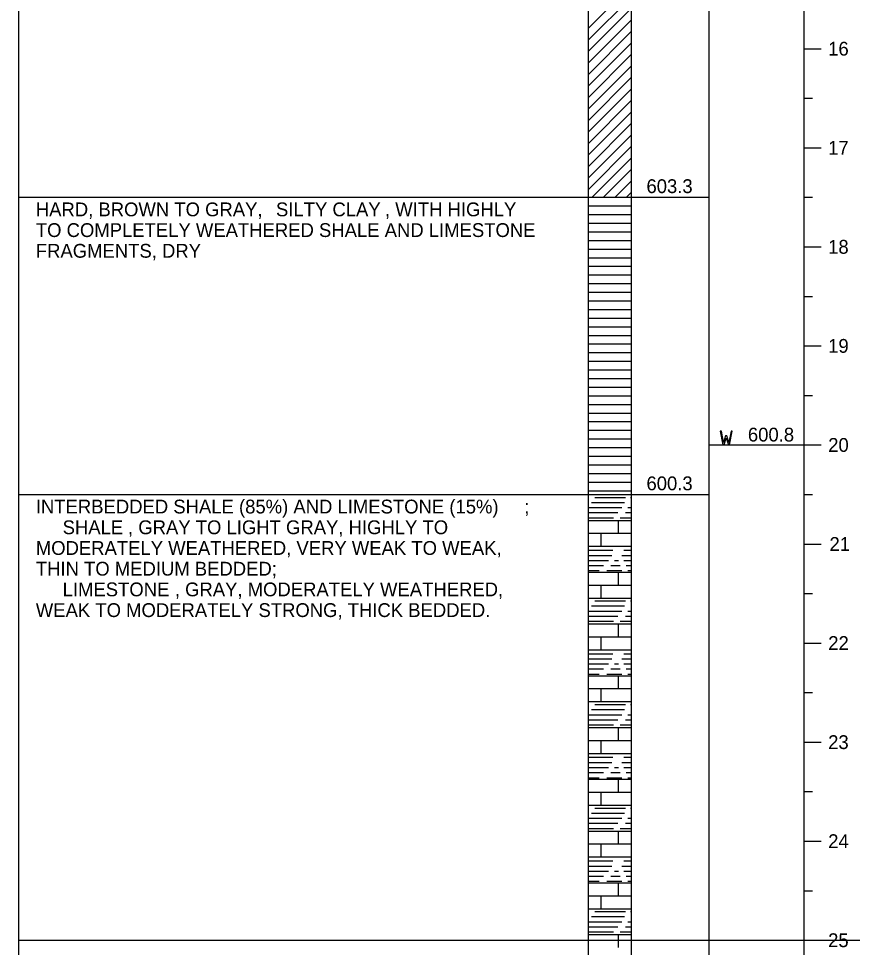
# Model space of a CAD drawing. Extents: x 0 to 0.83, y -0.65 to 1.27.
# Drawn here: x 0 to 0.4026, y -0.0035 to 0.4451 of the extents above; entities that cross this region are included whole.
import ezdxf

# ---------------------------------------------------------------- set-up
doc = ezdxf.new("R2010")
doc.units = 0

# ---------------------------------------------------------------- blocks, each defined once
blk = doc.blocks.new('DGRFC!OHDOT FREE WATER')
blk.add_lwpolyline([(-0.00161, 0), (-0.00102, 0), (0, 0.00346), (0.00102, 0), (0.00161, 0), (0.00292, 0.00667), (0.00233, 0.00667), (0.00126, 0.00118), (0.00029, 0.00444), (-0.00029, 0.00444), (-0.00126, 0.00118), (-0.00233, 0.00667), (-0.00292, 0.00667)], close=True)

msp = doc.modelspace()

# ---------------------------------------------------------------- linework, layer by layer
msp.add_lwpolyline([(0, 0), (0.83333, 0), (0.83333, 1.275), (0, 1.275)], close=True)
msp.add_lwpolyline([(0, 0), (0.83333, 0), (0.83333, 1.275), (0, 1.275)], close=True)
msp.add_lwpolyline([(0, 0), (0.83333, 0), (0.83333, 1.275), (0, 1.275)], close=True)
msp.add_lwpolyline([(0, 0), (0.83333, 0), (0.83333, 1.275), (0, 1.275)], close=True)
msp.add_lwpolyline([(0, 0), (0.83333, 0), (0.83333, 1.275), (0, 1.275)], close=True)
for points in [[(0.29583, 1.22083), (0.29583, -0.64575)], [(0.29583, 1.22083), (0.29583, -0.64575)], [(0.33333, 1.22083), (0.33333, -0.64575)], [(0.33333, 1.22083), (0.33333, -0.64575)], [(0.275, 1.19583), (0.275, -0.64575)], [(0.37917, 1.19583), (0.37917, -0.64575)], [(0.275, 0.64575), (0.275, 0.35875)], [(0.275, 0.44019), (0.29583, 0.46103)], [(0.275, 0.43464), (0.29583, 0.45547)], [(0.275, 0.42908), (0.29583, 0.44992)], [(0.275, 0.42353), (0.29583, 0.44436)], [(0.275, 0.41797), (0.29583, 0.4388)], [(0.275, 0.41242), (0.29583, 0.43325)], [(0.275, 0.40686), (0.29583, 0.42769)], [(0.37917, 0.4305), (0.3875, 0.4305)], [(0.37917, 0.4305), (0.38333, 0.4305)], [(0.275, 0.4013), (0.29583, 0.42214)], [(0.275, 0.39575), (0.29583, 0.41658)], [(0.275, 0.39019), (0.29583, 0.41103)], [(0.275, 0.38464), (0.29583, 0.40547)], [(0.37917, 0.40658), (0.38333, 0.40658)], [(0.275, 0.37908), (0.29583, 0.39992)], [(0.275, 0.37353), (0.29583, 0.39436)], [(0.275, 0.36797), (0.29583, 0.3888)], [(0.275, 0.36242), (0.29583, 0.38325)], [(0.37917, 0.38267), (0.3875, 0.38267)], [(0.37917, 0.38267), (0.38333, 0.38267)], [(0.27689, 0.35875), (0.29583, 0.37769)], [(0.28244, 0.35875), (0.29583, 0.37214)], [(0.288, 0.35875), (0.29583, 0.36658)], [(0.29355, 0.35875), (0.29583, 0.36103)], [(0, 0.35875), (0.275, 0.35875)], [(0.275, 0.35875), (0.29583, 0.35875)], [(0.275, 0.35875), (0.29583, 0.35875)], [(0.275, 0.35875), (0.275, 0.21525)], [(0.275, 0.35458), (0.29583, 0.35458)], [(0.29583, 0.35875), (0.33333, 0.35875)], [(0.37917, 0.35875), (0.38333, 0.35875)], [(0.275, 0.35042), (0.29583, 0.35042)], [(0.275, 0.34625), (0.29583, 0.34625)], [(0.275, 0.34208), (0.29583, 0.34208)], [(0.275, 0.33792), (0.29583, 0.33792)], [(0.275, 0.33375), (0.29583, 0.33375)], [(0.37917, 0.33483), (0.3875, 0.33483)], [(0.37917, 0.33483), (0.38333, 0.33483)], [(0.275, 0.32958), (0.29583, 0.32958)], [(0.275, 0.32542), (0.29583, 0.32542)], [(0.275, 0.32125), (0.29583, 0.32125)], [(0.275, 0.31708), (0.29583, 0.31708)], [(0.275, 0.31292), (0.29583, 0.31292)], [(0.37917, 0.31092), (0.38333, 0.31092)], [(0.275, 0.30875), (0.29583, 0.30875)], [(0.275, 0.30458), (0.29583, 0.30458)], [(0.275, 0.30042), (0.29583, 0.30042)], [(0.275, 0.29625), (0.29583, 0.29625)], [(0.275, 0.29208), (0.29583, 0.29208)], [(0.275, 0.28792), (0.29583, 0.28792)], [(0.275, 0.28375), (0.29583, 0.28375)], [(0.37917, 0.287), (0.3875, 0.287)], [(0.37917, 0.287), (0.38333, 0.287)], [(0.275, 0.27958), (0.29583, 0.27958)], [(0.275, 0.27542), (0.29583, 0.27542)], [(0.275, 0.27125), (0.29583, 0.27125)], [(0.275, 0.26708), (0.29583, 0.26708)], [(0.275, 0.26292), (0.29583, 0.26292)], [(0.37917, 0.26308), (0.38333, 0.26308)], [(0.275, 0.25875), (0.29583, 0.25875)], [(0.275, 0.25458), (0.29583, 0.25458)], [(0.275, 0.25042), (0.29583, 0.25042)], [(0.275, 0.24625), (0.29583, 0.24625)], [(0.275, 0.24208), (0.29583, 0.24208)], [(0.275, 0.23792), (0.29583, 0.23792)], [(0.33333, 0.23917), (0.37917, 0.23917)], [(0.37917, 0.23917), (0.3875, 0.23917)], [(0.37917, 0.23917), (0.38333, 0.23917)], [(0.275, 0.23375), (0.29583, 0.23375)], [(0.275, 0.22958), (0.29583, 0.22958)], [(0.275, 0.22542), (0.29583, 0.22542)], [(0.275, 0.22125), (0.29583, 0.22125)], [(0.275, 0.21708), (0.29583, 0.21708)], [(0, 0.21525), (0.275, 0.21525)], [(0.275, 0.21525), (0.29583, 0.21525)], [(0.275, 0.21525), (0.29583, 0.21525)], [(0.275, 0.21525), (0.275, -0.64575)], [(0.27667, 0.21142), (0.29258, 0.21142)], [(0.27825, 0.21383), (0.293, 0.21383)], [(0.29542, 0.21383), (0.29583, 0.21383)], [(0.29583, 0.21525), (0.33333, 0.21525)], [(0.37917, 0.21525), (0.38333, 0.21525)], [(0.275, 0.20892), (0.29133, 0.20892)], [(0.275, 0.2065), (0.28933, 0.2065)], [(0.293, 0.2065), (0.29583, 0.2065)], [(0.29417, 0.20892), (0.29583, 0.20892)], [(0.275, 0.204), (0.28725, 0.204)], [(0.275, 0.20275), (0.29583, 0.20275)], [(0.28958, 0.1965), (0.28958, 0.20275)], [(0.2905, 0.204), (0.29583, 0.204)], [(0.275, 0.1965), (0.29583, 0.1965)], [(0.28125, 0.19025), (0.28125, 0.1965)], [(0.275, 0.19025), (0.29583, 0.19025)], [(0.37917, 0.19133), (0.3875, 0.19133)], [(0.37917, 0.19133), (0.38333, 0.19133)], [(0.275, 0.18833), (0.28683, 0.18833)], [(0.275, 0.18583), (0.28642, 0.18583)], [(0.29133, 0.18583), (0.29583, 0.18583)], [(0.29217, 0.18833), (0.29583, 0.18833)], [(0.275, 0.18342), (0.28483, 0.18342)], [(0.275, 0.181), (0.28233, 0.181)], [(0.286, 0.181), (0.2905, 0.181)], [(0.28767, 0.18342), (0.28967, 0.18342)], [(0.29217, 0.18342), (0.29583, 0.18342)], [(0.29342, 0.181), (0.29583, 0.181)], [(0.275, 0.1785), (0.28033, 0.1785)], [(0.275, 0.17775), (0.29583, 0.17775)], [(0.284, 0.1785), (0.29133, 0.1785)], [(0.28958, 0.1715), (0.28958, 0.17775)], [(0.29417, 0.1785), (0.29583, 0.1785)], [(0.275, 0.1715), (0.29583, 0.1715)], [(0.28125, 0.16525), (0.28125, 0.1715)], [(0.37917, 0.16742), (0.38333, 0.16742)], [(0.275, 0.16525), (0.29583, 0.16525)], [(0.27825, 0.16383), (0.293, 0.16383)], [(0.29542, 0.16383), (0.29583, 0.16383)], [(0.275, 0.15892), (0.29133, 0.15892)], [(0.27667, 0.16142), (0.29258, 0.16142)], [(0.29417, 0.15892), (0.29583, 0.15892)], [(0.275, 0.1565), (0.28933, 0.1565)], [(0.275, 0.154), (0.28725, 0.154)], [(0.275, 0.15275), (0.29583, 0.15275)], [(0.28958, 0.1465), (0.28958, 0.15275)], [(0.2905, 0.154), (0.29583, 0.154)], [(0.293, 0.1565), (0.29583, 0.1565)], [(0.275, 0.1465), (0.29583, 0.1465)], [(0.28125, 0.14025), (0.28125, 0.1465)], [(0.275, 0.14025), (0.29583, 0.14025)], [(0.37917, 0.1435), (0.3875, 0.1435)], [(0.37917, 0.1435), (0.38333, 0.1435)], [(0.275, 0.13833), (0.28683, 0.13833)], [(0.275, 0.13583), (0.28642, 0.13583)], [(0.29133, 0.13583), (0.29583, 0.13583)], [(0.29217, 0.13833), (0.29583, 0.13833)], [(0.275, 0.13342), (0.28483, 0.13342)], [(0.275, 0.131), (0.28233, 0.131)], [(0.286, 0.131), (0.2905, 0.131)], [(0.28767, 0.13342), (0.28967, 0.13342)], [(0.29217, 0.13342), (0.29583, 0.13342)], [(0.29342, 0.131), (0.29583, 0.131)], [(0.275, 0.1285), (0.28033, 0.1285)], [(0.275, 0.12775), (0.29583, 0.12775)], [(0.284, 0.1285), (0.29133, 0.1285)], [(0.28958, 0.1215), (0.28958, 0.12775)], [(0.29417, 0.1285), (0.29583, 0.1285)], [(0.275, 0.1215), (0.29583, 0.1215)], [(0.28125, 0.11525), (0.28125, 0.1215)], [(0.37917, 0.11958), (0.38333, 0.11958)], [(0.275, 0.11525), (0.29583, 0.11525)], [(0.27825, 0.11383), (0.293, 0.11383)], [(0.29542, 0.11383), (0.29583, 0.11383)], [(0.275, 0.10892), (0.29133, 0.10892)], [(0.27667, 0.11142), (0.29258, 0.11142)], [(0.29417, 0.10892), (0.29583, 0.10892)], [(0.275, 0.1065), (0.28933, 0.1065)], [(0.275, 0.104), (0.28725, 0.104)], [(0.2905, 0.104), (0.29583, 0.104)], [(0.293, 0.1065), (0.29583, 0.1065)], [(0.275, 0.10275), (0.29583, 0.10275)], [(0.28958, 0.0965), (0.28958, 0.10275)], [(0.275, 0.0965), (0.29583, 0.0965)], [(0.28125, 0.09025), (0.28125, 0.0965)], [(0.37917, 0.09567), (0.3875, 0.09567)], [(0.37917, 0.09567), (0.38333, 0.09567)], [(0.275, 0.09025), (0.29583, 0.09025)], [(0, 0.0875), (0, -0.025), (0.83333, -0.025), (0.83333, 0.0875)], [(0.275, 0.08833), (0.28683, 0.08833)], [(0.275, 0.08583), (0.28642, 0.08583)], [(0.29133, 0.08583), (0.29583, 0.08583)], [(0.29217, 0.08833), (0.29583, 0.08833)], [(0.275, 0.08342), (0.28483, 0.08342)], [(0.275, 0.081), (0.28233, 0.081)], [(0.286, 0.081), (0.2905, 0.081)], [(0.28767, 0.08342), (0.28967, 0.08342)], [(0.29217, 0.08342), (0.29583, 0.08342)], [(0.29342, 0.081), (0.29583, 0.081)], [(0.275, 0.0785), (0.28033, 0.0785)], [(0.275, 0.07775), (0.29583, 0.07775)], [(0.284, 0.0785), (0.29133, 0.0785)], [(0.28958, 0.0715), (0.28958, 0.07775)], [(0.29417, 0.0785), (0.29583, 0.0785)], [(0.275, 0.0715), (0.29583, 0.0715)], [(0.28125, 0.06525), (0.28125, 0.0715)], [(0.37917, 0.07175), (0.38333, 0.07175)], [(0.275, 0.06525), (0.29583, 0.06525)], [(0.27825, 0.06383), (0.293, 0.06383)], [(0.29542, 0.06383), (0.29583, 0.06383)], [(0.275, 0.05892), (0.29133, 0.05892)], [(0.27667, 0.06142), (0.29258, 0.06142)], [(0.29417, 0.05892), (0.29583, 0.05892)], [(0.275, 0.0565), (0.28933, 0.0565)], [(0.275, 0.054), (0.28725, 0.054)], [(0.2905, 0.054), (0.29583, 0.054)], [(0.293, 0.0565), (0.29583, 0.0565)], [(0.275, 0.05275), (0.29583, 0.05275)], [(0.28958, 0.0465), (0.28958, 0.05275)], [(0.275, 0.0465), (0.29583, 0.0465)], [(0.28125, 0.04025), (0.28125, 0.0465)], [(0.37917, 0.04783), (0.3875, 0.04783)], [(0.37917, 0.04783), (0.38333, 0.04783)], [(0.275, 0.04025), (0.29583, 0.04025)], [(0.275, 0.03833), (0.28683, 0.03833)], [(0.29217, 0.03833), (0.29583, 0.03833)], [(0.275, 0.03583), (0.28642, 0.03583)], [(0.275, 0.03342), (0.28483, 0.03342)], [(0.28767, 0.03342), (0.28967, 0.03342)], [(0.29133, 0.03583), (0.29583, 0.03583)], [(0.29217, 0.03342), (0.29583, 0.03342)], [(0.275, 0.031), (0.28233, 0.031)], [(0.275, 0.0285), (0.28033, 0.0285)], [(0.275, 0.02775), (0.29583, 0.02775)], [(0.284, 0.0285), (0.29133, 0.0285)], [(0.286, 0.031), (0.2905, 0.031)], [(0.28958, 0.0215), (0.28958, 0.02775)], [(0.29342, 0.031), (0.29583, 0.031)], [(0.29417, 0.0285), (0.29583, 0.0285)], [(0.37917, 0.02392), (0.38333, 0.02392)], [(0.275, 0.0215), (0.29583, 0.0215)], [(0.28125, 0.01525), (0.28125, 0.0215)], [(0.275, 0.01525), (0.29583, 0.01525)], [(0.27825, 0.01383), (0.293, 0.01383)], [(0.29542, 0.01383), (0.29583, 0.01383)], [(0.27667, 0.01142), (0.29258, 0.01142)], [(0.275, 0.00892), (0.29133, 0.00892)], [(0.275, 0.0065), (0.28933, 0.0065)], [(0.293, 0.0065), (0.29583, 0.0065)], [(0.29417, 0.00892), (0.29583, 0.00892)], [(0, 0), (0.83333, 0)], [(0.275, 0.004), (0.28725, 0.004)], [(0.275, 0.00275), (0.29583, 0.00275)], [(0.28958, -0.0035), (0.28958, 0.00275)], [(0.2905, 0.004), (0.29583, 0.004)], [(0.37917, 0), (0.3875, 0)], [(0.37917, 0), (0.38333, 0)]]:
    msp.add_lwpolyline(points)

# ---------------------------------------------------------------- block references
msp.add_blockref('DGRFC!OHDOT FREE WATER', (0.34167, 0.23917))

# ---------------------------------------------------------------- texts
for s, height, p in [('16', 0.006667, (0.39087, 0.42717)), ('17', 0.006667, (0.39087, 0.37933)), ('603.3', 0.006667, (0.30314, 0.36079)), ('HARD, BROWN TO GRAY, ', 0.0066667, (0.00833, 0.34958)), ('SILTY CLAY', 0.006667, (0.12427, 0.34958)), (', WITH HIGHLY', 0.0066667, (0.1769, 0.34958)), ('TO COMPLETELY WEATHERED SHALE AND LIMESTONE', 0.0066667, (0.00833, 0.33958)), ('18', 0.006667, (0.39086, 0.3315)), ('FRAGMENTS, DRY', 0.0066667, (0.00833, 0.32958)), ('19', 0.006667, (0.39086, 0.28367)), ('600.8', 0.006667, (0.35211, 0.24083)), ('20', 0.006667, (0.39088, 0.23583)), ('600.3', 0.006667, (0.30314, 0.21729)), ('INTERBEDDED SHALE (85%) AND LIMESTONE (15%)', 0.0066667, (0.00833, 0.20608)), (';', 0.00667, (0.24416, 0.20608)), ('SHALE', 0.006667, (0.02127, 0.19608)), (', GRAY TO LIGHT GRAY, HIGHLY TO', 0.0066667, (0.05284, 0.19608)), ('21', 0.006667, (0.39151, 0.188)), ('MODERATELY WEATHERED, VERY WEAK TO WEAK,', 0.0066667, (0.00833, 0.18608)), ('THIN TO MEDIUM BEDDED;', 0.0066667, (0.00833, 0.17608)), ('LIMESTONE', 0.006667, (0.02127, 0.16608)), (', GRAY, MODERATELY WEATHERED,', 0.0066667, (0.07544, 0.16608)), ('WEAK TO MODERATELY STRONG, THICK BEDDED.', 0.0066667, (0.00833, 0.15608)), ('22', 0.006667, (0.3909, 0.14017)), ('23', 0.006667, (0.39087, 0.09233)), ('24', 0.006667, (0.39088, 0.0445)), ('25', 0.006667, (0.39084, -0.00333))]:
    msp.add_text(s, height=height).set_placement(p)

doc.saveas('drawing.dxf')
